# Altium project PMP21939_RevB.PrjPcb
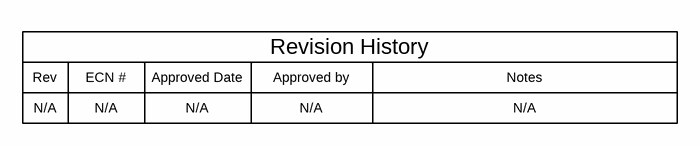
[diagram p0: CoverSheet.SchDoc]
TID: N/A; TechSupport: http://www.ti.com/support; SCH_Rev: B; PRJ_Number: PMP21939; PRJ_Engineer: Sahana Krishnan; PRJ_Customer: Public Release; PCB_Rev: B; PCB_Layout: Sahana Krishnan; CopyrightYear: 2019
4 sheets, 130 parts. Net scope: global (net labels, ports and power ports of the same name join across sheets).
Board file: PMP21939_PCB.PcbDoc
Sheets:
  CoverSheet.SchDoc
  Hardware.SchDoc
  PMP21939_Bus+Load Switches.SchDoc
  PMP21939_Load Converters.SchDoc

## Sheet CoverSheet.SchDoc
size 431 x 279 mm; Date: Not shown in title block; ApprovedBy: Not shown in title block; CheckedBy: Not shown in title block; Author: Not shown in title block; CompanyName: Not shown in title block; Engineer: Not shown in title block; Organization: Not shown in title block; Address1: Not shown in title block; Address2: Not shown in title block; Address3: Not shown in title block; Address4: Not shown in title block; DocumentNumber: 1; Revision: Use project parameter SCH_Rev; SheetNumber: 1; SheetTotal: 3; PageSetup: Record=PageOptions¦CenterHorizontal=True¦CenterVertical=True¦PrintScale=1.00¦XCorrection=1.00¦YCorrection=1.00¦PrintKind=0¦BorderSize=5000000¦LeftOffset=0¦BottomOffset=0¦Orientation=2¦PaperLength=1000¦PaperWidth=1000¦Scale=100¦PaperSource=15¦PrintQuality=600¦MediaType=1¦DitherType=10¦PaperKind=Letter¦PrintScaleMode=1

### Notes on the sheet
- Rev
- N/A
- ECN #
- Approved Date
- Approved by
- Revision History
- Notes

## Sheet Hardware.SchDoc
size 431 x 279 mm; Date: Not shown in title block; ApprovedBy: Not shown in title block; CheckedBy: Not shown in title block; Author: Not shown in title block; CompanyName: Not shown in title block; Engineer: Not shown in title block; Organization: Not shown in title block; Address1: Not shown in title block; Address2: Not shown in title block; Address3: Not shown in title block; Address4: Not shown in title block; DocumentNumber: 3; Revision: Use project parameter SCH_Rev; SheetNumber: 5; SheetTotal: 3; PageSetup: Record=PageOptions¦CenterHorizontal=True¦CenterVertical=True¦PrintScale=1.00¦XCorrection=1.00¦YCorrection=1.00¦PrintKind=0¦BorderSize=5000000¦LeftOffset=0¦BottomOffset=0¦Orientation=2¦PaperLength=1000¦PaperWidth=1000¦Scale=100¦PaperSource=15¦PrintQuality=600¦MediaType=1¦DitherType=10¦PaperKind=Letter¦PrintScaleMode=1
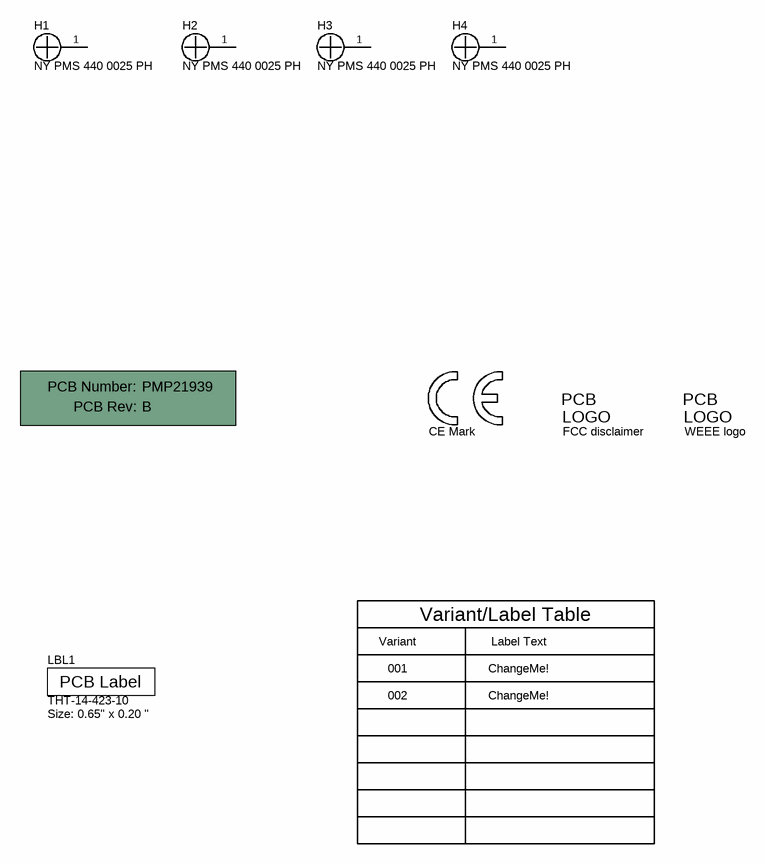
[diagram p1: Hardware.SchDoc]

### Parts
!PCB1  Printed Circuit Board  (value not drawn)  (mechanical)
H1  NY PMS 440 0025 PH  [NY PMS 440 0025 PH]
H2  NY PMS 440 0025 PH  [NY PMS 440 0025 PH]
H3  NY PMS 440 0025 PH  [NY PMS 440 0025 PH]
H4  NY PMS 440 0025 PH  [NY PMS 440 0025 PH]
LBL1  THT-14-423-10  Note: Size: 0.65" x 0.20 "  [Label_650x200]
Logo1  CE Mark  [CE_Mark_5mm]  (no BOM)
Logo3  FCC disclaimer  [FCC_disclaimer]  (no BOM)
Logo4  WEEE logo  [WEEE_Minimum]  (no BOM)

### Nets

Not connected (* = marked no-connect by the designer): H1 1; H2 1; H3 1; H4 1

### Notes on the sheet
- Variant
- Variant/Label Table
- Label Text
- 001
- 002
- ChangeMe!

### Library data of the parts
!PCB1 = CMP-0003618-2: Manufacturer: Any; PartNumber: PMP21939
H1-H4 = CMP-0003617-1: Machine Screw, Round, #4-40 x 1/4, Nylon, Philips panhead; Manufacturer: B&F Fastener Supply; CompType: Hardware
LBL1 = CMP-0003625-1: Thermal Transfer Printable Labels, 0.650" W x 0.200" H - 10,000 per roll; Manufacturer: Brady; CompType: Label
Logo1 = CMP-0074844-1: SymbolCreator: a0412235
Logo3 = CMP-0074847-1: FCC_disclaimer; Library Reference: Logo
Logo4 = CMP-0074769-1

## Sheet PMP21939_Bus+Load Switches.SchDoc
size 431 x 279 mm; Date: Not shown in title block; ApprovedBy: Not shown in title block; CheckedBy: Not shown in title block; Author: Not shown in title block; CompanyName: Not shown in title block; Engineer: Not shown in title block; Organization: Not shown in title block; Address1: Not shown in title block; Address2: Not shown in title block; Address3: Not shown in title block; Address4: Not shown in title block; DocumentNumber: 2; Revision: Use project parameter SCH_Rev; SheetNumber: 2; SheetTotal: 3; PageSetup: Record=PageOptions¦CenterHorizontal=True¦CenterVertical=True¦PrintScale=1.00¦XCorrection=1.00¦YCorrection=1.00¦PrintKind=0¦BorderSize=5000000¦LeftOffset=0¦BottomOffset=0¦Orientation=2¦PaperLength=1000¦PaperWidth=1000¦Scale=100¦PaperSource=15¦PrintQuality=600¦MediaType=1¦DitherType=10¦PaperKind=Letter¦PrintScaleMode=1
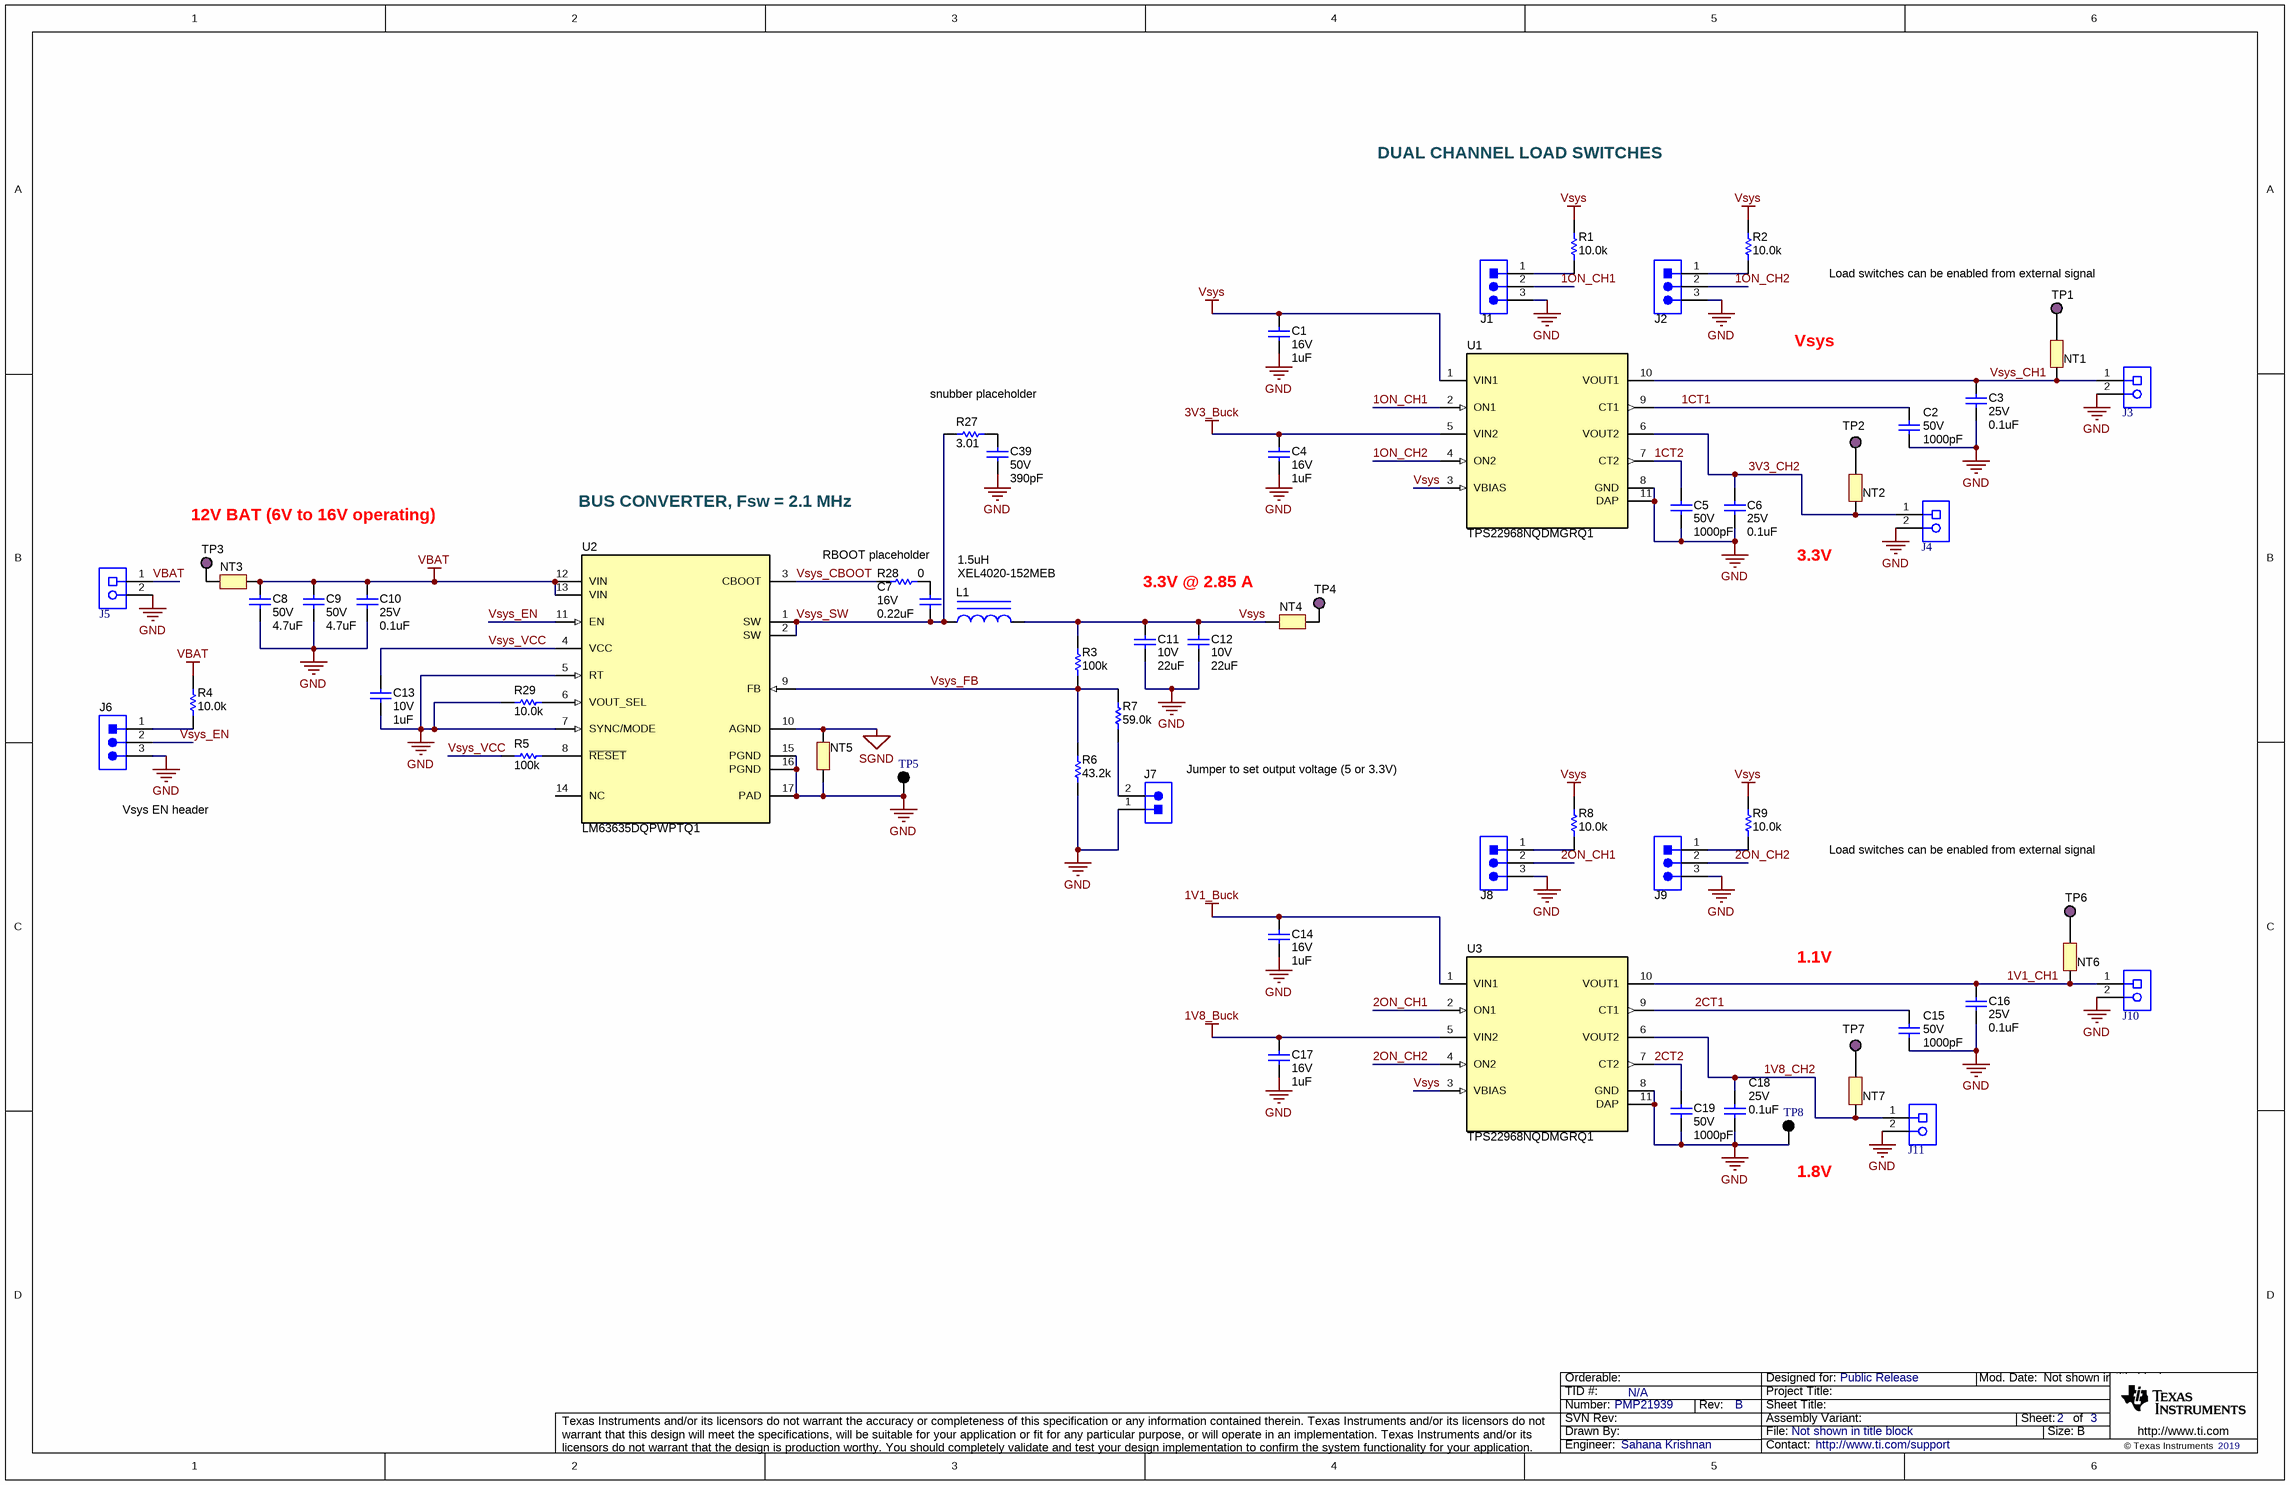
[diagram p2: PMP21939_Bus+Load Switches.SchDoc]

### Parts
C1  VDC_V: 16V  ValueDisplayed: 1uF  [0603]  (hidden comment: GCM188R71C105MA64D)
C2  VDC_V: 50V  ValueDisplayed: 1000pF  [0402]  (hidden comment: CGA2B2X7R1H102K050BA)
C3  VDC_V: 25V  ValueDisplayed: 0.1uF  [0603]  (hidden comment: CGA3E2X7R1E104K080AA)
C4  VDC_V: 16V  ValueDisplayed: 1uF  [0603]  (hidden comment: GCM188R71C105MA64D)
C5  VDC_V: 50V  ValueDisplayed: 1000pF  [0402]  (hidden comment: CGA2B2X7R1H102K050BA)
C6  VDC_V: 25V  ValueDisplayed: 0.1uF  [0603]  (hidden comment: CGA3E2X7R1E104K080AA)
C7  VDC_V: 16V  ValueDisplayed: 0.22uF  [0402]  (hidden comment: C1005X7R1C224K050BC)
C8  VDC_V: 50V  ValueDisplayed: 4.7uF  [1210_280]  (hidden comment: CGA6P3X7R1H475K250AB)
C9  VDC_V: 50V  ValueDisplayed: 4.7uF  [1210_280]  (hidden comment: CGA6P3X7R1H475K250AB)
C10  VDC_V: 25V  ValueDisplayed: 0.1uF  [0603]  (hidden comment: CGA3E2X7R1E104K080AA)
C11  VDC_V: 10V  ValueDisplayed: 22uF  [1206_180]  (hidden comment: GCM31CR71A226KE02)
C12  VDC_V: 10V  ValueDisplayed: 22uF  [1206_180]  (hidden comment: GCM31CR71A226KE02)
C13  VDC_V: 10V  ValueDisplayed: 1uF  [0402_070]  (hidden comment: GCM155C71A105KE38D)
C14  VDC_V: 16V  ValueDisplayed: 1uF  [0603]  (hidden comment: GCM188R71C105MA64D)
C15  VDC_V: 50V  ValueDisplayed: 1000pF  [0402]  (hidden comment: CGA2B2X7R1H102K050BA)
C16  VDC_V: 25V  ValueDisplayed: 0.1uF  [0603]  (hidden comment: CGA3E2X7R1E104K080AA)
C17  VDC_V: 16V  ValueDisplayed: 1uF  [0603]  (hidden comment: GCM188R71C105MA64D)
C18  VDC_V: 25V  ValueDisplayed: 0.1uF  [0603]  (hidden comment: CGA3E2X7R1E104K080AA)
C19  VDC_V: 50V  ValueDisplayed: 1000pF  [0402]  (hidden comment: CGA2B2X7R1H102K050BA)
C39  VDC_V: 50V  ValueDisplayed: 390pF  [0402]  (hidden comment: GCM155R71H391KA37D)
J1  800-10-003-10-001000  [Mill-Max_800-10-003-10-001000]  (value not drawn)
J2  800-10-003-10-001000  [Mill-Max_800-10-003-10-001000]  (value not drawn)
J3  ED555/2DS  [TERM_BLK_ED555-2DS]  (value not drawn)
J4  ED555/2DS  [TERM_BLK_ED555-2DS]  (value not drawn)
J5  ED555/2DS  [TERM_BLK_ED555-2DS]  (value not drawn)
J6  800-10-003-10-001000  [Mill-Max_800-10-003-10-001000]  (value not drawn)
J7  TSW-102-07-G-S  [TSW-102-07-G-S]  (value not drawn)
J8  800-10-003-10-001000  [Mill-Max_800-10-003-10-001000]  (value not drawn)
J9  800-10-003-10-001000  [Mill-Max_800-10-003-10-001000]  (value not drawn)
J10  ED555/2DS  [TERM_BLK_ED555-2DS]  (value not drawn)
J11  ED555/2DS  [TERM_BLK_ED555-2DS]  (value not drawn)
L1  ValueDisplayed: 1.5uH  [XEL4020]  (hidden comment: XEL4020-152MEB)
NT1  Net-Tie  [Net-Tie_10mil]  (value not drawn)  (net tie, no BOM)
NT2  Net-Tie  [Net-Tie_10mil]  (value not drawn)  (net tie, no BOM)
NT3  Net-Tie  [Net-Tie_10mil]  (value not drawn)  (net tie, no BOM)
NT4  Net-Tie  [Net-Tie_10mil]  (value not drawn)  (net tie, no BOM)
NT5  Net-Tie  [Net-Tie_10mil]  (value not drawn)  (net tie, no BOM)
NT6  Net-Tie  [Net-Tie_10mil]  (value not drawn)  (net tie, no BOM)
NT7  Net-Tie  [Net-Tie_10mil]  (value not drawn)  (net tie, no BOM)
R1  ValueDisplayed: 10.0k  [0402]  (hidden comment: ERJPA2F1002X)
R2  ValueDisplayed: 10.0k  [0402]  (hidden comment: ERJPA2F1002X)
R3  ValueDisplayed: 100k  [0402]  (hidden comment: RMCF0402FT100K)
R4  ValueDisplayed: 10.0k  [0402]  (hidden comment: ERJPA2F1002X)
R5  ValueDisplayed: 100k  [0402]  (hidden comment: RMCF0402FT100K)
R6  ValueDisplayed: 43.2k  [0402]  (hidden comment: CRCW040243K2FKED)
R7  ValueDisplayed: 59.0k  [0402]  (hidden comment: CRCW040259K0FKED)
R8  ValueDisplayed: 10.0k  [0402]  (hidden comment: ERJPA2F1002X)
R9  ValueDisplayed: 10.0k  [0402]  (hidden comment: ERJPA2F1002X)
R27  ValueDisplayed: 3.01  [0402]  (hidden comment: CRCW04023R01FKED)
R28  ValueDisplayed: 0  [0402]  (hidden comment: CRCW04020000Z0EDHP)
R29  ValueDisplayed: 10.0k  [0402]  (hidden comment: ERJPA2F1002X)
TP1  5129  [Keystone5129]  (value not drawn)
TP2  5129  [Keystone5129]  (value not drawn)
TP3  5129  [Keystone5129]  (value not drawn)
TP4  5129  [Keystone5129]  (value not drawn)
TP5  5011  [Keystone5011]  (value not drawn)
TP6  5129  [Keystone5129]  (value not drawn)
TP7  5129  [Keystone5129]  (value not drawn)
TP8  5011  [Keystone5011]  (value not drawn)
U1  TPS22968NQDMGRQ1  [DMG0010A]
U2  LM63635DQPWPTQ1  [PWP0016K_N]
U3  TPS22968NQDMGRQ1  [DMG0010A]

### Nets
1V1_Buck: C14.1 U3.1(VIN1)
1V8_Buck: C17.1 U3.5(VIN2)
3V3_Buck: C4.1 U1.5(VIN2)
GND: C1.2 C2.2 C3.2 C4.2 C5.2 C6.2 C8.2 C9.2 C10.2 C11.2 C12.2 C13.2 C14.2 C15.2 C16.2 C17.2 C18.2 C19.2 C39.1 J1.3 J2.3 J3.2 J4.2 J5.2 J6.3 J7.1 J8.3 J9.3 J10.2 J11.2 NT5.1 R6.1 R29.2 TP5.1 TP8.1 U1.8(GND) U1.11(DAP) U2.5(RT) U2.7(SYNC/MODE) U2.15(PGND) U2.16(PGND) U2.17(PAD) U3.8(GND) U3.11(DAP)
SGND: NT5.2 U2.10(AGND)
VBAT: C8.1 C9.1 C10.1 J5.1 NT3.2 R4.2 U2.12(VIN) U2.13(VIN)
Vsys: C1.1 C11.1 C12.1 L1.2 NT4.1 R1.2 R2.2 R3.2 R8.2 R9.2 U1.1(VIN1) U1.3(VBIAS) U3.3(VBIAS)
1CT1: C2.1 U1.9(CT1)
1CT2: C5.1 U1.7(CT2)
1ON_CH1: J1.2 U1.2(ON1)
1ON_CH2: J2.2 U1.4(ON2)
1V1_CH1: C16.1 J10.1 NT6.1 U3.10(VOUT1)
1V8_CH2: C18.1 J11.1 NT7.1 U3.6(VOUT2)
2CT1: C15.1 U3.9(CT1)
2CT2: C19.1 U3.7(CT2)
2ON_CH1: J8.2 U3.2(ON1)
2ON_CH2: J9.2 U3.4(ON2)
3V3_CH2: C6.1 J4.1 NT2.1 U1.6(VOUT2)
Vsys_CBOOT: R28.2 U2.3(CBOOT)
Vsys_CH1: C3.1 J3.1 NT1.1 U1.10(VOUT1)
Vsys_EN: J6.2 U2.11(EN)
Vsys_FB: R3.1 R6.2 R7.2 U2.9(FB)
Vsys_SW: C7.2 L1.1 R27.1 U2.1(SW) U2.2(SW)
Vsys_VCC: C13.1 R5.2 U2.4(VCC)
NetC7_1: C7.1 R28.1
NetC39_2: C39.2 R27.2
NetJ1_1: J1.1 R1.1
NetJ2_1: J2.1 R2.1
NetJ6_1: J6.1 R4.1
NetJ7_2: J7.2 R7.1
NetJ8_1: J8.1 R8.1
NetJ9_1: J9.1 R9.1
NetNT1_2: NT1.2 TP1.1
NetNT2_2: NT2.2 TP2.1
NetNT3_1: NT3.1 TP3.1
NetNT4_2: NT4.2 TP4.1
NetNT6_2: NT6.2 TP6.1
NetNT7_2: NT7.2 TP7.1
NetR5_1: R5.1 U2.8(~{RESET})
NetR29_1: R29.1 U2.6(VOUT_SEL)

Not connected (* = marked no-connect by the designer): U2 14(NC)

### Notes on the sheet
- DUAL CHANNEL LOAD SWITCHES
- (near TP1) Load switches can be enabled from external signal
- Vsys
- snubber placeholder
- BUS CONVERTER, Fsw = 2.1 MHz
- 12V BAT (6V to 16V operating)
- RBOOT placeholder
- 3.3V
- 3.3V @ 2.85 A
- (near J7) Jumper to set output voltage (5 or 3.3V)
- (near J6) Vsys EN header
- Load switches can be enabled from external signal
- 1.1V
- (near TP8) 1.8V

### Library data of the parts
C1 C4 C14 C17 = CMP-0007137-1: CAP, CERM, 1 uF, 16 V, +/- 20%, X7R, AEC-Q200 Grade 1, 0603; Manufacturer: MuRata; TaMin_C: -55°C; Polarized: N; SizeAreaWB_mm2: 4.68; Value1: Unknown; U/M: EA; Value: 1uF; TaMax_C: 125°C; SizeZ_mm: 1; SizeX_mm: 1.6; SizeY_mm: 0.8; SizeArea_mm2: 1.28; AEC Qualified: Y; Cap_F: 1µF; AEC Category: Q200
C2 C5 C15 C19 = CMP-0006314-2: CAP, CERM, 1000 pF, 50 V, +/- 10%, X7R, AEC-Q200 Grade 1, 0402; Manufacturer: TDK; TaMin_C: -55°C; ESR_ohm: 2.25564; Polarized: N; SizeAreaWB_mm2: 3; Value1: 2.25564 ohm; U/M: EA; Value: 1000pF; TaMax_C: 125°C; SizeZ_mm: 0.6; SizeX_mm: 1; SizeY_mm: 0.5; AEC Qualified: Y; Cap_F: 1nF; IRMS_A: 280.466mA; AEC Category: Q200
C3 C6 C10 C16 C18 = CMP-0007077-5: CAP, CERM, 0.1 uF, 25 V, +/- 10%, X7R, AEC-Q200 Grade 1, 0603; Manufacturer: TDK; TaMin_C: -55°C; Polarized: N; SizeAreaWB_mm2: 4.68; Value1: Unknown; U/M: EA; Value: 0.1uF; TaMax_C: 125°C; SizeZ_mm: 1; SizeX_mm: 1.6; SizeY_mm: 0.8; SizeArea_mm2: 1.28; AEC Qualified: Y; Cap_F: 100nF; AEC Category: Q200
C7 = CMP-0006293-1: CAP, CERM, 0.22 uF, 16 V, +/- 10%, X7R, 0402; Manufacturer: TDK; TaMin_C: -55°C; Polarized: N; SizeAreaWB_mm2: 3; Value1: Unknown; U/M: EA; Value: 0.22uF; TaMax_C: 125°C; SizeZ_mm: 0.6; SizeX_mm: 1; SizeY_mm: 0.5; Cap_F: 220nF; AEC Category: Q200
C8 C9 = CMP-0009162-2: CAP, CERM, 4.7 uF, 50 V, +/- 10%, X7R, AEC-Q200 Grade 1, 1210; Manufacturer: TDK; TaMin_C: -55°C; ESR_ohm: 3.166m; Polarized: N; SizeAreaWB_mm2: 14.7; Value1: 0.003166 ohm; U/M: EA; Value: 4.7uF; TaMax_C: 125°C; SizeZ_mm: 2.8; SizeX_mm: 3.2; SizeY_mm: 2.5; SizeArea_mm2: 8; AEC Qualified: Y; Cap_F: 4.7µF; IRMS_A: 4.13311A; AEC Grade: 1; AEC Category: Q200
C11 C12 = CMP-0008811-1: CAP, CERM, 22 uF, 10 V, +/- 10%, X7R, AEC-Q200 Grade 1, 1206; Manufacturer: MuRata; TaMin_C: -55°C; Polarized: N; SizeAreaWB_mm2: 10.92; Value1: Unknown; U/M: EA; Value: 22uF; TaMax_C: 125°C; SizeZ_mm: 1.8; SizeX_mm: 3.2; SizeY_mm: 1.6; Cap_Case: 1206; SizeArea_mm2: 5.12; AEC Qualified: Y; Cap_F: 22µF; AEC Grade: 1; AEC Category: Q200
C13 = CMP-0006349-1: CAP, CERM, 1 uF, 10 V, +/- 10%, X7S, AEC-Q200 Grade 1, 0402; Manufacturer: MuRata; TaMin_C: -55°C; Polarized: N; SizeAreaWB_mm2: 3; Value1: Unknown; U/M: EA; Value: 1uF; TaMax_C: 125°C; SizeZ_mm: 0.7; SizeX_mm: 1; SizeY_mm: 0.5; Cap_Case: 0402; AEC Qualified: Y; Cap_F: 1µF; AEC Category: Q200
C39 = CMP-0080703-2: CAP, CERM, 390 pF, 50 V,+/- 10%, X7R, AEC-Q200 Grade 1, 0402; Manufacturer: MuRata; SizeX_mm: 1; SizeZ_mm: 0.6; SizeY_mm: 0.5; AEC Qualified: Y; Value: 390pF; Polarized: N; AEC Category: Q200; TaMax_C: 125°C; TaMin_C: -55°C; SizeAreaWB_mm2: 3; U/M: EA
J1 J2 J6 J8 J9 = CMP-0055086-1: Header, 100mil, 3x1, TH; Manufacturer: Mill-Max; CNHeader: TRUE; Green_Lifecycle: Active; Green_REACh: Passed; CT: FALSE
J3-J5 J10 J11 = CMP-0074913-1: Terminal Block, 3.5mm Pitch, 2x1, TH; Manufacturer: On-Shore Technology; Cert_VDE: Y; CNHeader: False; Current_A: 6A; Green_Lifecycle: Active; Shrouded: N; Gender: Female; Green_REACh: Passed; Voltage_V: 150V; Row_Count: 1; Pitch_mm: 3.5; ContactFinish: Brass; CT: True
J7 = CMP-0075405-2: Header, 100mil, 2x1, Gold, TH; Manufacturer: Samtec; Pitch_mm: 2.54; Cert_VDE: N; Gender: Male; Cert_CSA: Y; Voltage_V: 550V; Green_REACh: Passed; Current_A: 6.3A; Green_Lifecycle: Active; Row_Count: 1
L1 = CMP-0061077-2: Inductor, Shielded, Composite, 1.5 uH, 7.4 A, 0.0215 ohm, AEC-Q200 Grade 1, SMD; Manufacturer: Coilcraft; Isat: 7.4A @ 30% inductance drop; Irms: 7.5A @ 40C rise; SizeAreaWB_mm2: 25; DCR_ohm: 0.0215; Value: 1.5uH; Imax_A: 7.4A; SizeZ_mm: 2.1; SizeX_mm: 4; SizeArea_mm2: 16; Ind_H: 1.5µH; AEC Qualified: Y; AEC Grade: 1; AEC Category: Q200
NT1-NT4 NT6 NT7 = CMP-0078142-1: Single point connection between nets.
NT5 = CMP-0078142-2: Single point connection between nets.
R1 R2 R4 R8 R9 R29 = CMP-0078779-1: RES, 10.0 k, 1%, 0.2 W, AEC-Q200 Grade 0, 0402; Manufacturer: Panasonic; Value_Code: 10k0; SizeArea_mm2: 0.5; AEC Qualified: Y; AEC Category: Q200; Res_ohm: 10k; Value: 10.0k; SizeZ_mm: 0.6; EIA_Code: E96; TempCo: 100 ppm/C; AEC Grade: 0; Power_W: 200mW; VDC_V: 50V; Value2: 0.2W; SizeX_mm: 1
R3 R5 = CMP-0026753-1: RES, 100 k, 1%, 0.063 W, AEC-Q200 Grade 0, 0402; Manufacturer: Stackpole Electronics Inc; Power_W: 63mW; TempCo: 100 ppm/C; U/M: EA; Value: 100k; EIA_Code: E96; SizeX_mm: 1; SizeY_mm: 0.5; SizeZ_mm: 0.6; Value2: 0.063W; AEC Qualified: Y; VDC_V: 50V; AEC Grade: 0; AEC Category: Q200
R6 = CMP-0026379-2: RES, 43.2 k, 1%, 0.063 W, AEC-Q200 Grade 0, 0402; Manufacturer: Vishay-Dale; Power_W: 63mW; TempCo: 100 ppm/C; Value_Code: 43k2; Value: 43.2k; EIA_Code: E96; SizeX_mm: 1; SizeY_mm: 0.5; SizeZ_mm: 0.6; Value2: 0.063W; AEC Qualified: Y; VDC_V: 50V; AEC Category: Q200; AEC Grade: 0
R7 = CMP-0026461-2: RES, 59.0 k, 1%, 0.063 W, AEC-Q200 Grade 0, 0402; Manufacturer: Vishay-Dale; Power_W: 63mW; TempCo: 100 ppm/C; Value_Code: 59k0; Value: 59.0k; EIA_Code: E96; Res_ohm: 59k; SizeX_mm: 1; SizeY_mm: 0.5; SizeZ_mm: 0.6; Value2: 0.063W; AEC Qualified: Y; VDC_V: 50V; AEC Category: Q200; AEC Grade: 0
R27 = CMP-0026353-2: RES, 3.01, 1%, 0.063 W, AEC-Q200 Grade 0, 0402; Manufacturer: Vishay-Dale; Power_W: 63mW; TempCo: 100 ppm/C; Value_Code: 3R01; Value: 3.01; EIA_Code: E96; SizeX_mm: 1; SizeY_mm: 0.5; SizeZ_mm: 0.6; Value2: 0.063W; AEC Qualified: Y; VDC_V: 50V; AEC Category: Q200; AEC Grade: 0
R28 = CMP-0081856-1: RES, 0, 0%, 0.2 W, AEC-Q200 Grade 0, 0402; Manufacturer: Vishay-Dale; SizeAreaWB_mm2: 3; SizeArea_mm2: 0.5; AEC Qualified: Y; AEC Category: Q200; Value: 0; SizeZ_mm: 0.6; Power_W: 200mW; VDC_V: 50V; Value2: 0.2W; SizeX_mm: 1
TP1-TP4 TP6 TP7 = CMP-0055160-1: Test Point, Multipurpose, Purple, TH; Manufacturer: Keystone; CNHeader: FALSE; ContactFinish: Silver; CT: TRUE
TP5 TP8 = CMP-0055148-1: Test Point, Multipurpose, Black, TH; Manufacturer: Keystone; CNHeader: FALSE; Green_Lifecycle: Active; Green_REACh: Passed; ContactFinish: Silver; CT: TRUE
U1 U3 = CMP-0073682-2: 5.5V, 4A, 27mΩ, 2-Ch Automotive Load Switch With Quick Output Discharge and Adjustable Rise Time, DMG0010A (WSON-10); Alternate Manufacturer: Texas Instruments; Green_Lifecycle: Active; SizeAreaWB_mm2: 12.0; Green_REACh: Passed; U/M: EA; SizeZ_mm: 0.8; SizeX_mm: 2.0; SizeY_mm: 3.0; SizeArea_mm2: 6.0; CompType: IC
U2 = CMP-0080079-4: 3.5-V to 36-V, 3.5-A Synchronous Step-Down Voltage Regulator with Spread Spectrum, PWP0016D (TSSOP-16); Alternate Manufacturer: Texas Instruments; SizeAreaWB_mm2: 58.8; SizeZ_mm: 1.2; SizeX_mm: 6.4; SizeY_mm: 5; SizeArea_mm2: 32; CompType: IC; AEC Qualified: Y; AEC Category: Q200; Rating: Automotive

## Sheet PMP21939_Load Converters.SchDoc
size 431 x 279 mm; Date: Not shown in title block; ApprovedBy: Not shown in title block; CheckedBy: Not shown in title block; Author: Not shown in title block; CompanyName: Not shown in title block; Engineer: Not shown in title block; Organization: Not shown in title block; Address1: Not shown in title block; Address2: Not shown in title block; Address3: Not shown in title block; Address4: Not shown in title block; DocumentNumber: 2; Revision: Use project parameter SCH_Rev; SheetNumber: 3; SheetTotal: 3; PageSetup: Record=PageOptions¦CenterHorizontal=True¦CenterVertical=True¦PrintScale=1.00¦XCorrection=1.00¦YCorrection=1.00¦PrintKind=0¦BorderSize=5000000¦LeftOffset=0¦BottomOffset=0¦Orientation=2¦PaperLength=1000¦PaperWidth=1000¦Scale=100¦PaperSource=15¦PrintQuality=600¦MediaType=1¦DitherType=10¦PaperKind=Letter¦PrintScaleMode=1
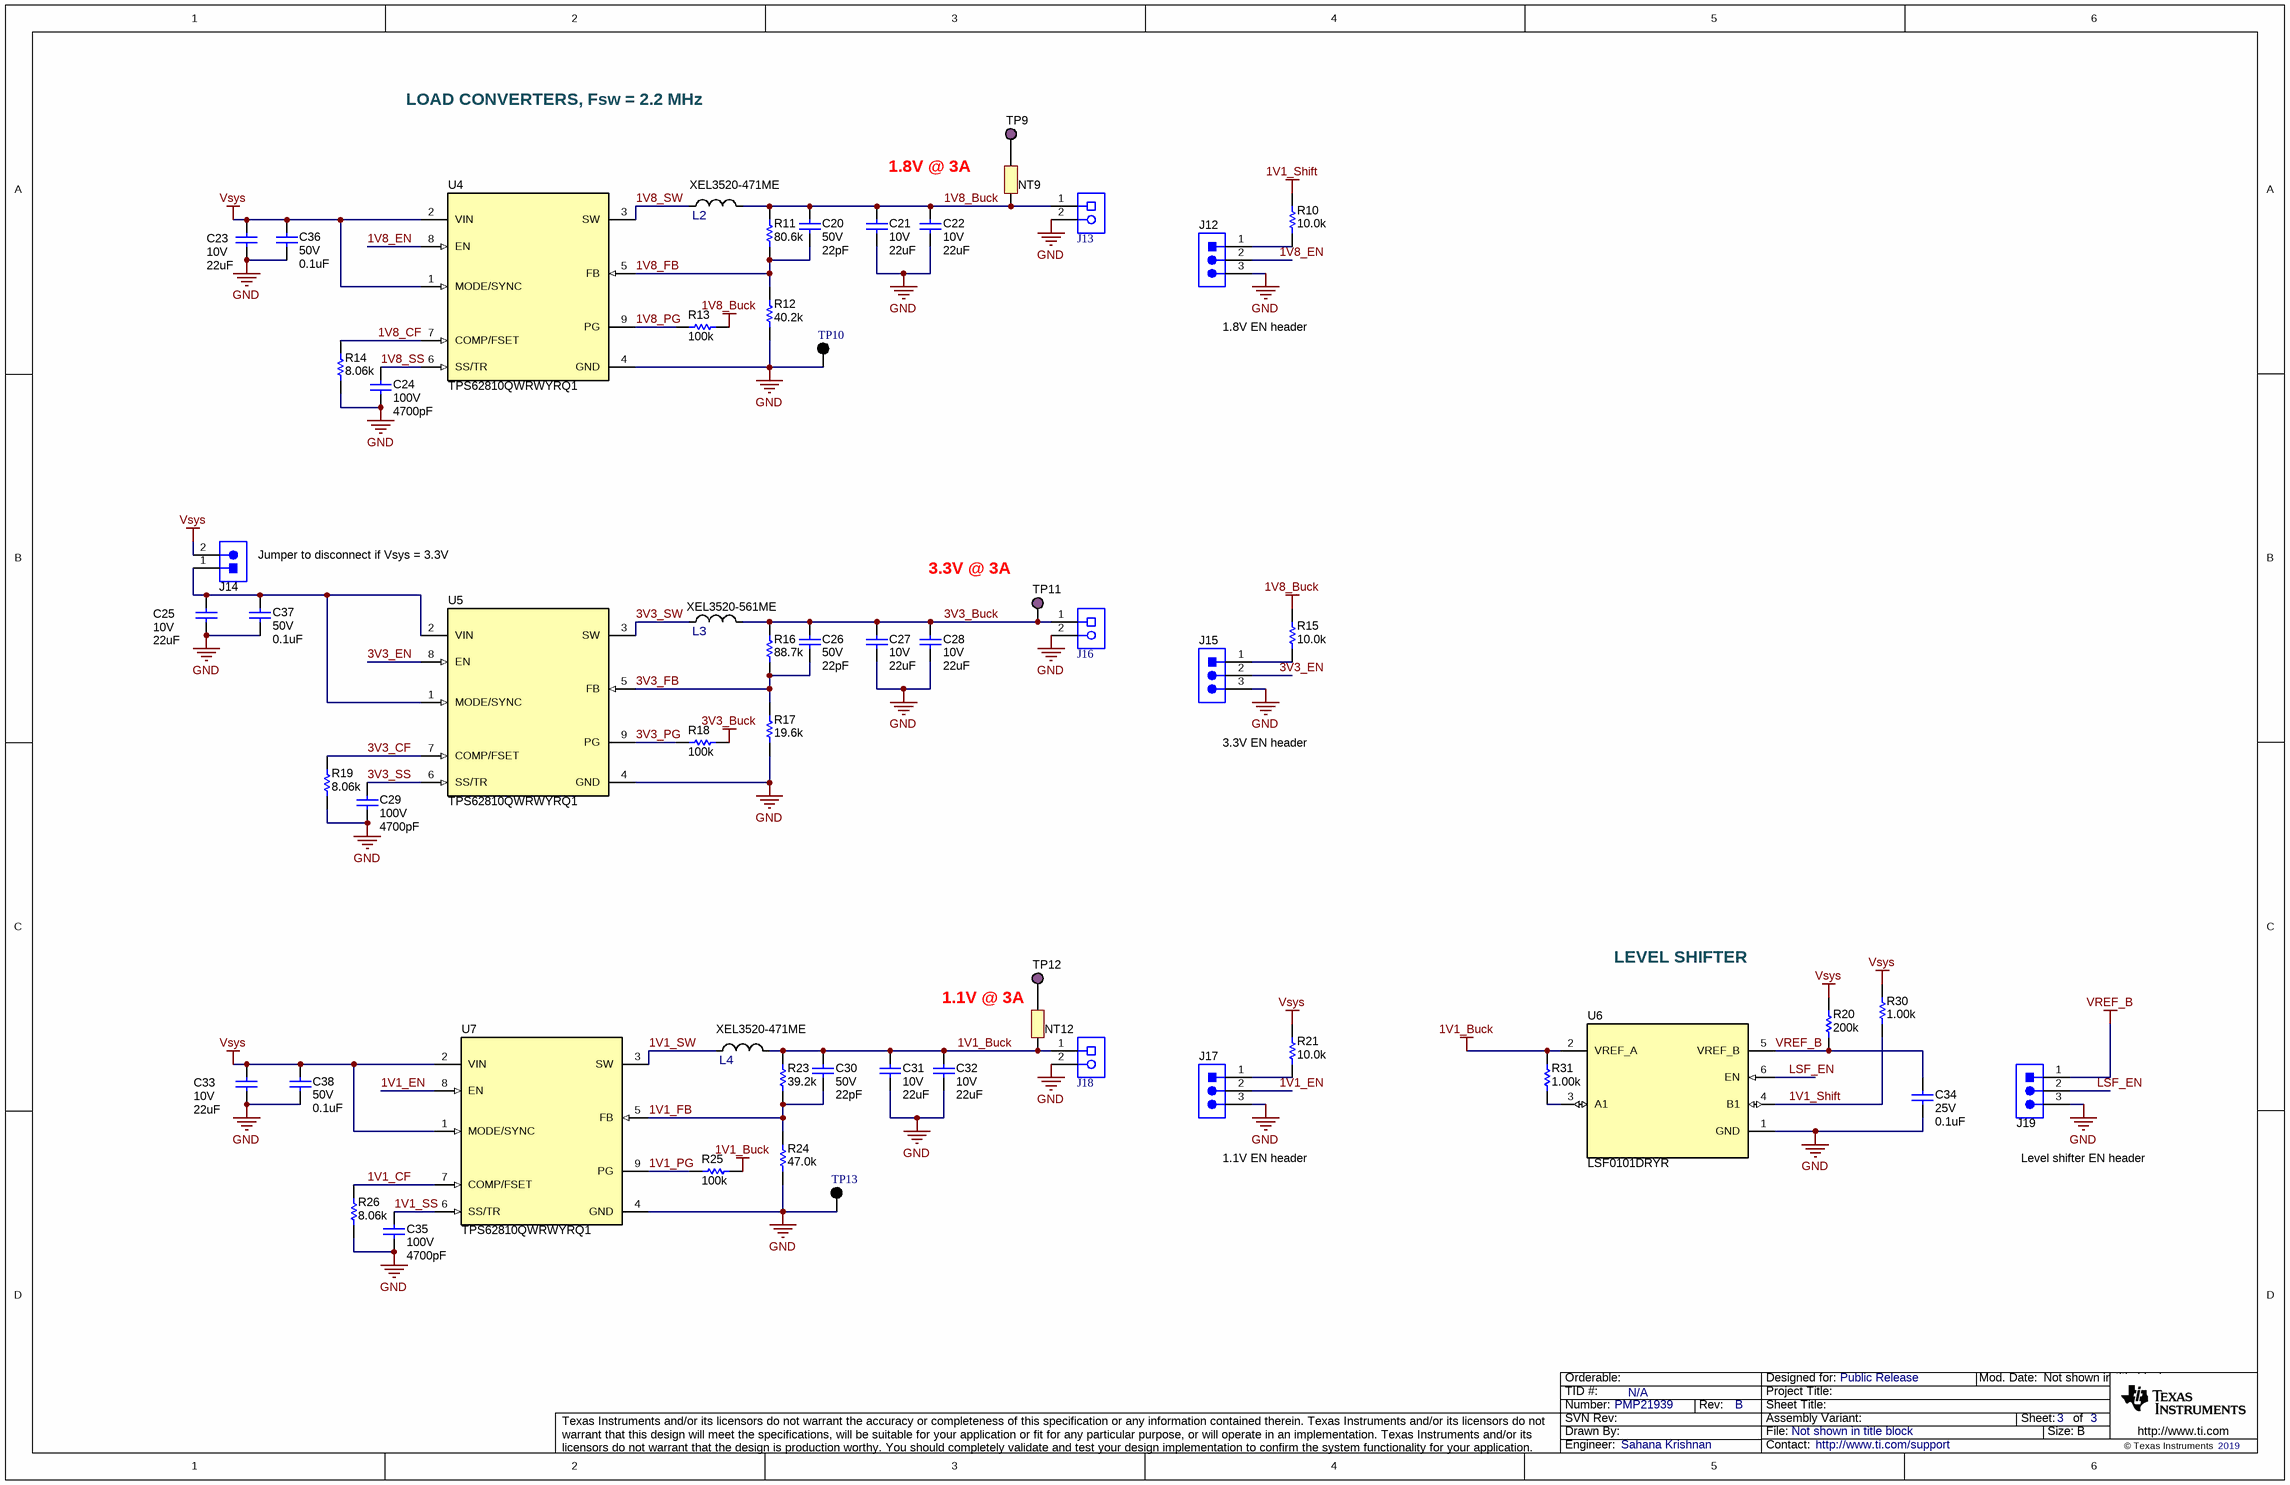
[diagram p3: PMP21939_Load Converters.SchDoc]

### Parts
C20  VDC_V: 50V  ValueDisplayed: 22pF  [0402]  (hidden comment: CGA2B2NP01H220J050BA)
C21  VDC_V: 10V  ValueDisplayed: 22uF  [1206_180]  (hidden comment: GCM31CR71A226KE02)
C22  VDC_V: 10V  ValueDisplayed: 22uF  [1206_180]  (hidden comment: GCM31CR71A226KE02)
C23  VDC_V: 10V  ValueDisplayed: 22uF  [1206_180]  (hidden comment: GCM31CR71A226KE02)
C24  VDC_V: 100V  ValueDisplayed: 4700pF  [0402]  (hidden comment: CGA2B3X7S2A472K050BB)
C25  VDC_V: 10V  ValueDisplayed: 22uF  [1206_180]  (hidden comment: GCM31CR71A226KE02)
C26  VDC_V: 50V  ValueDisplayed: 22pF  [0402]  (hidden comment: CGA2B2NP01H220J050BA)
C27  VDC_V: 10V  ValueDisplayed: 22uF  [1206_180]  (hidden comment: GCM31CR71A226KE02)
C28  VDC_V: 10V  ValueDisplayed: 22uF  [1206_180]  (hidden comment: GCM31CR71A226KE02)
C29  VDC_V: 100V  ValueDisplayed: 4700pF  [0402]  (hidden comment: CGA2B3X7S2A472K050BB)
C30  VDC_V: 50V  ValueDisplayed: 22pF  [0402]  (hidden comment: CGA2B2NP01H220J050BA)
C31  VDC_V: 10V  ValueDisplayed: 22uF  [1206_180]  (hidden comment: GCM31CR71A226KE02)
C32  VDC_V: 10V  ValueDisplayed: 22uF  [1206_180]  (hidden comment: GCM31CR71A226KE02)
C33  VDC_V: 10V  ValueDisplayed: 22uF  [1206_180]  (hidden comment: GCM31CR71A226KE02)
C34  VDC_V: 25V  ValueDisplayed: 0.1uF  [0603]  (hidden comment: CGA3E2X7R1E104K080AA)
C35  VDC_V: 100V  ValueDisplayed: 4700pF  [0402]  (hidden comment: CGA2B3X7S2A472K050BB)
C36  VDC_V: 50V  ValueDisplayed: 0.1uF  [0402]  (hidden comment: CGA2B3X7R1H104K050BB)
C37  VDC_V: 50V  ValueDisplayed: 0.1uF  [0402]  (hidden comment: CGA2B3X7R1H104K050BB)
C38  VDC_V: 50V  ValueDisplayed: 0.1uF  [0402]  (hidden comment: CGA2B3X7R1H104K050BB)
J12  800-10-003-10-001000  [Mill-Max_800-10-003-10-001000]  (value not drawn)
J13  ED555/2DS  [TERM_BLK_ED555-2DS]  (value not drawn)
J14  TSW-102-07-G-S  [TSW-102-07-G-S]  (value not drawn)
J15  800-10-003-10-001000  [Mill-Max_800-10-003-10-001000]  (value not drawn)
J16  ED555/2DS  [TERM_BLK_ED555-2DS]  (value not drawn)
J17  800-10-003-10-001000  [Mill-Max_800-10-003-10-001000]  (value not drawn)
J18  ED555/2DS  [TERM_BLK_ED555-2DS]  (value not drawn)
J19  800-10-003-10-001000  [Mill-Max_800-10-003-10-001000]  (value not drawn)
L2  XEL3520-471ME  [FP-XEL3520-471ME_SMD2-MFG]
L3  XEL3520-561ME  [FP-XEL3520-561ME_SMT_IND_3MM2_3MM5-MFG]
L4  XEL3520-471ME  [FP-XEL3520-471ME_SMD2-MFG]
NT9  Net-Tie  [Net-Tie_10mil]  (value not drawn)  (net tie, no BOM)
NT12  Net-Tie  [Net-Tie_10mil]  (value not drawn)  (net tie, no BOM)
R10  ValueDisplayed: 10.0k  [0402]  (hidden comment: ERJPA2F1002X)
R11  ValueDisplayed: 80.6k  [0402]  (hidden comment: CRCW040280K6FKED)
R12  ValueDisplayed: 40.2k  [0402]  (hidden comment: CRCW040240K2FKED)
R13  ValueDisplayed: 100k  [0402]  (hidden comment: RMCF0402FT100K)
R14  ValueDisplayed: 8.06k  [0402]  (hidden comment: CRCW04028K06FKED)
R15  ValueDisplayed: 10.0k  [0402]  (hidden comment: ERJPA2F1002X)
R16  ValueDisplayed: 88.7k  [0402]  (hidden comment: CRCW040288K7FKED)
R17  ValueDisplayed: 19.6k  [0402]  (hidden comment: CRCW040219K6FKED)
R18  ValueDisplayed: 100k  [0402]  (hidden comment: RMCF0402FT100K)
R19  ValueDisplayed: 8.06k  [0402]  (hidden comment: CRCW04028K06FKED)
R20  ValueDisplayed: 200k  [0402]  (hidden comment: ERJ-2RKF2003X)
R21  ValueDisplayed: 10.0k  [0402]  (hidden comment: ERJPA2F1002X)
R23  ValueDisplayed: 39.2k  [0402]  (hidden comment: CRCW040239K2FKED)
R24  ValueDisplayed: 47.0k  [0402]  (hidden comment: RC0402FR-0747KL)
R25  ValueDisplayed: 100k  [0402]  (hidden comment: RMCF0402FT100K)
R26  ValueDisplayed: 8.06k  [0402]  (hidden comment: CRCW04028K06FKED)
R30  ValueDisplayed: 1.00k  [0402]  (hidden comment: CRCW04021K00FKED)
R31  ValueDisplayed: 1.00k  [0402]  (hidden comment: CRCW04021K00FKED)
TP9  5129  [Keystone5129]  (value not drawn)
TP10  5011  [Keystone5011]  (value not drawn)
TP11  5129  [Keystone5129]  (value not drawn)
TP12  5129  [Keystone5129]  (value not drawn)
TP13  5011  [Keystone5011]  (value not drawn)
U4  TPS62810QWRWYRQ1  [RWY0009A]
U5  TPS62810QWRWYRQ1  [RWY0009A]
U6  LSF0101DRYR  [DRY0006A]
U7  TPS62810QWRWYRQ1  [RWY0009A]

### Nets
1V1_Buck: C30.1 C31.1 C32.1 J18.1 L4.2 NT12.1 R23.2 R25.2 R31.2 U6.2(VREF_A)
1V1_Shift: R10.2 R30.1 U6.4(B1)
1V8_Buck: C20.1 C21.1 C22.1 J13.1 L2.2 NT9.1 R11.2 R13.2 R15.2
3V3_Buck: C26.1 C27.1 C28.1 J16.1 L3.2 R16.2 R18.2 TP11.1
GND: C21.2 C22.2 C23.2 C24.2 C25.2 C27.2 C28.2 C29.2 C31.2 C32.2 C33.2 C34.2 C35.2 C36.2 C37.2 C38.2 J12.3 J13.2 J15.3 J16.2 J17.3 J18.2 J19.3 R12.1 R14.1 R17.1 R19.1 R24.1 R26.1 TP10.1 TP13.1 U4.4(GND) U5.4(GND) U6.1(GND) U7.4(GND)
VREF_B: C34.1 J19.1 R20.1 U6.5(VREF_B)
Vsys: C23.1 C33.1 C36.1 C38.1 J14.2 R20.2 R21.2 R30.2 U4.1(MODE/SYNC) U4.2(VIN) U7.1(MODE/SYNC) U7.2(VIN)
1V1_CF: R26.2 U7.7(COMP/FSET)
1V1_EN: J17.2 U7.8(EN)
1V1_FB: C30.2 R23.1 R24.2 U7.5(FB)
1V1_PG: R25.1 U7.9(PG)
1V1_SS: C35.1 U7.6(SS/TR)
1V1_SW: L4.1 U7.3(SW)
1V8_CF: R14.2 U4.7(COMP/FSET)
1V8_EN: J12.2 U4.8(EN)
1V8_FB: C20.2 R11.1 R12.2 U4.5(FB)
1V8_PG: R13.1 U4.9(PG)
1V8_SS: C24.1 U4.6(SS/TR)
1V8_SW: L2.1 U4.3(SW)
3V3_CF: R19.2 U5.7(COMP/FSET)
3V3_EN: J15.2 U5.8(EN)
3V3_FB: C26.2 R16.1 R17.2 U5.5(FB)
3V3_PG: R18.1 U5.9(PG)
3V3_SS: C29.1 U5.6(SS/TR)
3V3_SW: L3.1 U5.3(SW)
LSF_EN: J19.2 U6.6(EN)
NetC25_1: C25.1 C37.1 J14.1 U5.1(MODE/SYNC) U5.2(VIN)
NetJ12_1: J12.1 R10.1
NetJ15_1: J15.1 R15.1
NetJ17_1: J17.1 R21.1
NetNT9_2: NT9.2 TP9.1
NetNT12_2: NT12.2 TP12.1
NetR31_1: R31.1 U6.3(A1)

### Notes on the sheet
- LOAD CONVERTERS, Fsw = 2.2 MHz
- 1.8V @ 3A
- (near J12) 1.8V EN header
- (near J14) Jumper to disconnect if Vsys = 3.3V
- 3.3V @ 3A
- (near J15) 3.3V EN header
- LEVEL SHIFTER
- 1.1V @ 3A
- (near J17) 1.1V EN header
- (near J19) Level shifter EN header

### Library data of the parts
C20 C26 C30 = CMP-0006311-2: CAP, CERM, 22 pF, 50 V, +/- 5%, C0G/NP0, AEC-Q200 Grade 1, 0402; Manufacturer: TDK; TaMin_C: -55°C; Polarized: N; SizeAreaWB_mm2: 3; Value1: Unknown; U/M: EA; Value: 22pF; TaMax_C: 125°C; SizeZ_mm: 0.6; SizeX_mm: 1; SizeY_mm: 0.5; AEC Qualified: Y; AEC Category: Q200
C21-C23 C25 C27 C28 C31-C33 = CMP-0008811-1: as C11 on sheet PMP21939_Bus+Load Switches
C24 C29 C35 = CMP-0006337-2: CAP, CERM, 4700 pF, 100 V, +/- 10%, X7S, AEC-Q200 Grade 1, 0402; Manufacturer: TDK; TaMin_C: -55°C; ESR_ohm: 0.685549; Polarized: N; SizeAreaWB_mm2: 3; Value1: 0.685549 ohm; U/M: EA; Value: 4700pF; TaMax_C: 125°C; SizeZ_mm: 0.6; SizeX_mm: 1; SizeY_mm: 0.5; AEC Qualified: Y; Cap_F: 4.7nF; IRMS_A: 263.706mA; AEC Category: Q200
C34 = CMP-0007077-5: as C3 on sheet PMP21939_Bus+Load Switches
C36-C38 = CMP-0006325-2: CAP, CERM, 0.1 uF, 50 V, +/- 10%, X7R, AEC-Q200 Grade 1, 0402; Manufacturer: TDK; TaMin_C: -55°C; ESR_ohm: 0.039064; Polarized: N; SizeAreaWB_mm2: 3; Value1: 0.039064 ohm; U/M: EA; Value: 0.1uF; TaMax_C: 125°C; SizeZ_mm: 0.6; SizeX_mm: 1; SizeY_mm: 0.5; AEC Qualified: Y; Cap_F: 100nF; IRMS_A: 814.669mA; AEC Category: Q200
J12 J15 J17 J19 = CMP-0055086-1: as J1 on sheet PMP21939_Bus+Load Switches
J13 J16 J18 = CMP-0074913-1: as J3 on sheet PMP21939_Bus+Load Switches
J14 = CMP-0075405-2: as J7 on sheet PMP21939_Bus+Load Switches
L2 L4 = CMP-0086402-1: Shielded Power Inductor,0.47uH, AEC-Q200; Manufacturer: Coilcraft; Isat: 8A; AEC Qualified: Yes; Imax_A: 12.1A; SizeZ_mm: 2mm; AEC Grade: Grade 1; Material: Composite; Symbol Name: SYM-XEL3520-471ME
L3 = CMP-0087074-1: Shielded Power Inductors; Manufacturer: Coilcraft; Symbol Name: SYM-XEL3520-561ME; AEC Grade: Grade 1; Isat: 7.3A; AEC Qualified: Yes; Irms: 10.1A; Material: Composite; SizeZ_mm: 2mm
NT9 NT12 = CMP-0078142-1: Single point connection between nets.
R10 R15 R21 = CMP-0078779-1: as R1 on sheet PMP21939_Bus+Load Switches
R11 = CMP-0026570-2: RES, 80.6 k, 1%, 0.063 W, AEC-Q200 Grade 0, 0402; Manufacturer: Vishay-Dale; Power_W: 63mW; TempCo: 100 ppm/C; Value_Code: 80k6; Value: 80.6k; EIA_Code: E96; SizeX_mm: 1; SizeY_mm: 0.5; SizeZ_mm: 0.6; Value2: 0.063W; AEC Qualified: Y; VDC_V: 50V; AEC Category: Q200; AEC Grade: 0
R12 = CMP-0026367-2: RES, 40.2 k, 1%, 0.063 W, AEC-Q200 Grade 0, 0402; Manufacturer: Vishay-Dale; Power_W: 63mW; TempCo: 100 ppm/C; Value_Code: 40k2; Value: 40.2k; EIA_Code: E96; SizeX_mm: 1; SizeY_mm: 0.5; SizeZ_mm: 0.6; Value2: 0.063W; AEC Qualified: Y; VDC_V: 50V; AEC Category: Q200; AEC Grade: 0
R13 R18 R25 = CMP-0026753-1: as R3 on sheet PMP21939_Bus+Load Switches
R14 R19 R26 = CMP-0026588-2: RES, 8.06 k, 1%, 0.063 W, AEC-Q200 Grade 0, 0402; Manufacturer: Vishay-Dale; Power_W: 63mW; TempCo: 100 ppm/C; Value_Code: 8k06; Value: 8.06k; EIA_Code: E96; SizeX_mm: 1; SizeY_mm: 0.5; SizeZ_mm: 0.6; Value2: 0.063W; AEC Qualified: Y; VDC_V: 50V; AEC Category: Q200; AEC Grade: 0
R16 = CMP-0026586-2: RES, 88.7 k, 1%, 0.063 W, AEC-Q200 Grade 0, 0402; Manufacturer: Vishay-Dale; Power_W: 63mW; TempCo: 100 ppm/C; Value_Code: 88k7; Value: 88.7k; EIA_Code: E96; SizeX_mm: 1; SizeY_mm: 0.5; SizeZ_mm: 0.6; Value2: 0.063W; AEC Qualified: Y; VDC_V: 50V; AEC Category: Q200; AEC Grade: 0
R17 = CMP-0026068-3: RES, 19.6 k, 1%, 0.063 W, AEC-Q200 Grade 0, 0402; Manufacturer: Vishay-Dale; Power_W: 63mW; TempCo: 100 ppm/C; Value_Code: 19k6; Value: 19.6k; EIA_Code: E96; SizeX_mm: 1; SizeY_mm: 0.5; SizeZ_mm: 0.6; Value2: 0.063W; AEC Qualified: Y; VDC_V: 50V; AEC Category: Q200; AEC Grade: 0
R20 = CMP-0026677-1: RES, 200 k, 1%, 0.1 W, 0402; Manufacturer: Panasonic; Power_W: 100mW; TempCo: 100 ppm/C; U/M: EA; Value: 200k; EIA_Code: E96; SizeX_mm: 1; SizeY_mm: 0.5; SizeZ_mm: 0.6; Value2: 0.1W; VDC_V: 50V; AEC Category: Q200
R23 = CMP-0026327-2: RES, 39.2 k, 1%, 0.063 W, AEC-Q200 Grade 0, 0402; Manufacturer: Vishay-Dale; Power_W: 63mW; TempCo: 100 ppm/C; Value_Code: 39k2; Value: 39.2k; EIA_Code: E96; SizeX_mm: 1; SizeY_mm: 0.5; SizeZ_mm: 0.6; Value2: 0.063W; AEC Qualified: Y; VDC_V: 50V; AEC Category: Q200; AEC Grade: 0
R24 = CMP-0026737-1: RES, 47.0 k, 1%, 0.0625 W, 0402; Manufacturer: Yageo America; Power_W: 62.5mW; TempCo: 100 ppm/C; Value_Code: 47k0; U/M: EA; Value: 47.0k; Res_ohm: 47k; SizeX_mm: 1; SizeY_mm: 0.5; SizeZ_mm: 0.6; AEC Qualified: N; VDC_V: 50V; AEC Category: Q200
R30 R31 = CMP-0026071-3: RES, 1.00 k, 1%, 0.063 W, AEC-Q200 Grade 0, 0402; Manufacturer: Vishay-Dale; Power_W: 63mW; TempCo: 100 ppm/C; Value_Code: 1k00; Value: 1.00k; EIA_Code: E96; Res_ohm: 1k; SizeX_mm: 1; SizeY_mm: 0.5; SizeZ_mm: 0.6; Value2: 0.063W; AEC Qualified: Y; VDC_V: 50V; AEC Category: Q200; AEC Grade: 0
TP9 TP11 TP12 = CMP-0055160-1: as TP1 on sheet PMP21939_Bus+Load Switches
TP10 TP13 = CMP-0055148-1: as TP5 on sheet PMP21939_Bus+Load Switches
U4 U5 U7 = CMP-0082642-1: Automotive Low Input Voltage, Adjustable-Frequency Step-down Converter, RWY0009A (VQFN-HR-9); Alternate Manufacturer: Texas Instruments; SizeAreaWB_mm2: 12; SizeZ_mm: 1; SizeX_mm: 2; SizeY_mm: 3; SizeArea_mm2: 6; CompType: IC; AEC Qualified: Y; AEC Category: Q200
U6 = CMP-0066431-3: Single Bi-Directional Multi-Voltage Level Translator, DRY0006A (USON-6); Manufacturer: Texas Instruments; Green_Lifecycle: Active; SizeAreaWB_mm2: 4.9; Green_REACh: Passed; SizeZ_mm: 0.6; SizeX_mm: 1.0; SizeY_mm: 1.45; CompType: IC; AEC Category: Q200; AEC Qualified: N; Rating: Catalog

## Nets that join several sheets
1V1_Buck: PMP21939_Bus+Load Switches (C14.1 U3.1), PMP21939_Load Converters (10 pins)
1V8_Buck: PMP21939_Bus+Load Switches (C17.1 U3.5), PMP21939_Load Converters (9 pins)
3V3_Buck: PMP21939_Bus+Load Switches (C4.1 U1.5), PMP21939_Load Converters (8 pins)
GND: PMP21939_Bus+Load Switches (44 pins), PMP21939_Load Converters (35 pins)
Vsys: PMP21939_Bus+Load Switches (13 pins), PMP21939_Load Converters (12 pins)

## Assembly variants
001: not fitted C39 FID1 FID2 FID3 R27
